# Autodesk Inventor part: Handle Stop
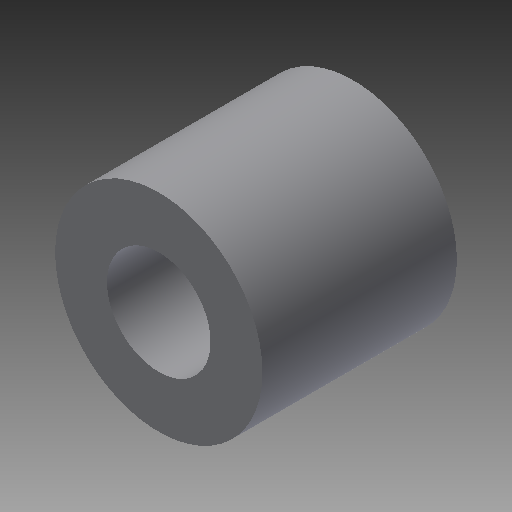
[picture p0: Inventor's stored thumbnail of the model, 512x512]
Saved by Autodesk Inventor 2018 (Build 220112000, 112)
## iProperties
Shininess: 77.0
Length Units: 11269
Angle Units: 11279
Time Units: 11290
Mass Units: 11283
Length Display Precision: 3
Angle Display Precision: 2
Compacted: True
Created: 2002-02
Part Number: Handle Stop
Document SubType Name: Modeling
Designer: ***
Density: 1 g/cm^3
Material: Generic
Appearance: Default
Density: 0.0
Volumn: 0.0
Area: 0.0
PropertySet Name: Model Information
Control State: 0
Master: False
Checked Out: False
Author: ***
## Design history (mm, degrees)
sketch "Sketch1"
  geometry: L1 (0, 0)-(0, -2); L2 (0, -2)-(8, -2); L3 (8, -2)-(8, 13); L4 (8, 13)-(4, 13); L5 (4, 13)-(4, 0); L6 (4, 0)-(0, 0)
  constraints: 12 end point, 4 parallel, 1 perpendicular, 1 vertical
  dimensions: "d0" = 16 diameter of L3 L1; "d1" = 8 diameter of L5 L1; "d2" = 2 distance of L1.start L1.end; "d3" = 15 distance of L2.end L3.end
revolve "Revolution1" sketch "Sketch1" stored, may be unused: angle "d4" = 90 deg
body "Solid1"
